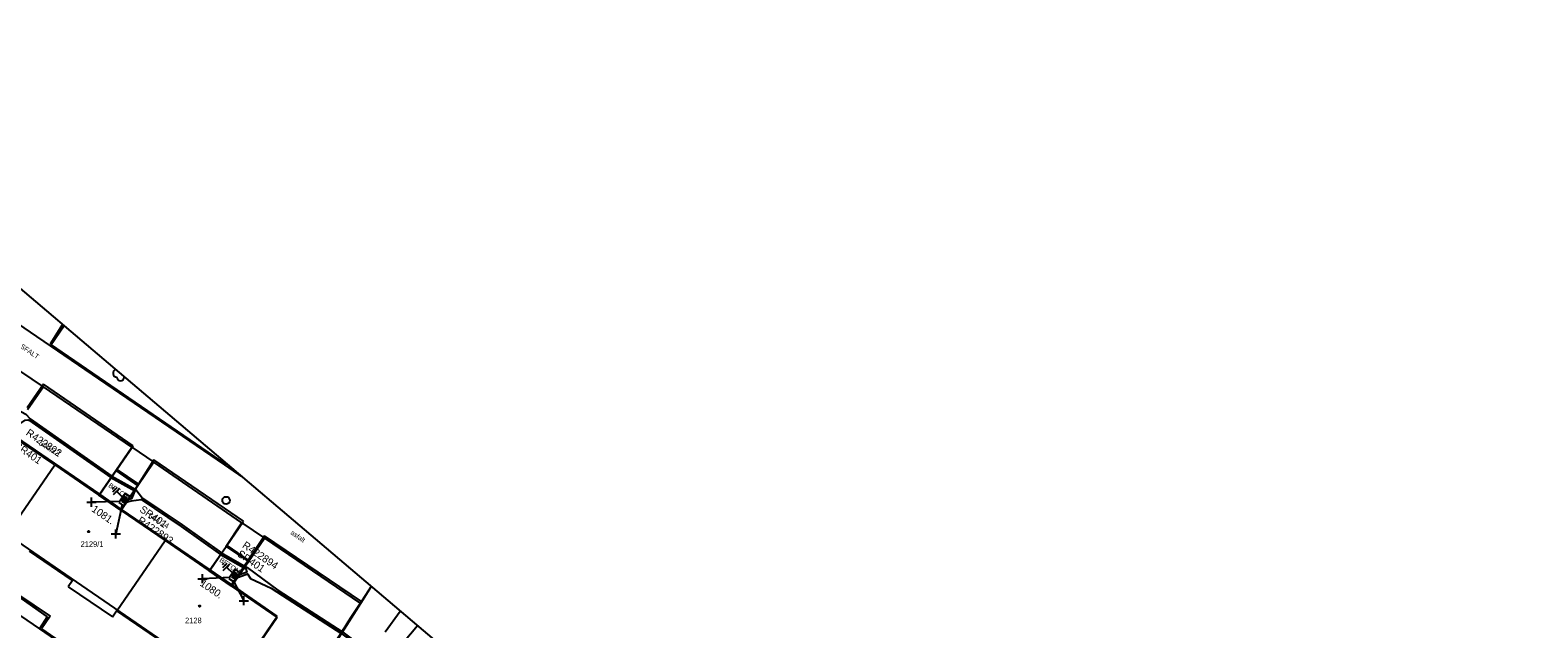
# Model space of a CAD drawing. Extents: x -540150 to -533593, y -1185082 to -1180066.
# Drawn here: x -536321.9 to -536119.2, y -1184312.1 to -1184231.5 of the extents above; entities that cross this region are included whole.
import ezdxf

# ---------------------------------------------------------------- set-up
doc = ezdxf.new("R2010")
doc.units = 0
for name, color, linetype in [('KN_HRAN_PARCEL', 7, 'Continuous'), ('KN_PARC_Č', 7, 'Continuous'), ('KN_VKP_HRAN_', 7, 'Continuous'), ('rámeček', 7, 'Continuous'), ('Vrstva 1', 7, 'Continuous'), ('Vrstva 10', 7, 'Continuous'), ('Vrstva 11', 7, 'Continuous'), ('Vrstva 14', 7, 'Continuous'), ('Vrstva 15', 7, 'Continuous'), ('Vrstva 22', 7, 'Continuous'), ('Vrstva 27', 7, 'Continuous'), ('Vrstva 28', 7, 'Continuous'), ('Vrstva 29', 7, 'Continuous'), ('Vrstva 30', 7, 'Continuous'), ('Vrstva 34', 7, 'Continuous'), ('Vrstva 39', 7, 'Continuous'), ('Vrstva 40', 7, 'Continuous'), ('Vrstva 47', 7, 'Continuous'), ('Vrstva 5', 7, 'Continuous'), ('Vrstva 59', 7, 'Continuous'), ('Vrstva 8', 7, 'Continuous')]:
    doc.layers.add(name, color=color, linetype=linetype)

# ---------------------------------------------------------------- blocks, each defined once
blk = doc.blocks.new('NN800')
at = {"layer": 'Vrstva 1'}
for points in [[(-0.44, 0.44), (0.44, -0.44)], [(-0.44, -0.44), (0.44, 0.44)]]:
    blk.add_lwpolyline(points, dxfattribs=at)
blk = doc.blocks.new('NN620')
at = {"layer": 'Vrstva 8'}
for points in [[(0.75, 0), (-0.75, 0)], [(-0.75, 0), (-0.75, -0.75)], [(0.75, -0.75), (0.75, 0)], [(-0.75, -0.75), (0.75, -0.75)], [(0.37, -0.18), (-0.38, -0.18)], [(-0.38, -0.18), (-0.38, -0.56)], [(-0.38, -0.56), (0.37, -0.56)], [(0.32, -0.23), (-0.33, -0.23)], [(-0.33, -0.23), (-0.33, -0.51)], [(-0.33, -0.51), (0.32, -0.51)], [(0.27, -0.27), (-0.28, -0.27)], [(-0.28, -0.27), (-0.28, -0.46)], [(-0.28, -0.46), (0.27, -0.46)], [(0.23, -0.32), (-0.23, -0.32)], [(-0.23, -0.32), (-0.23, -0.42)], [(-0.23, -0.42), (0.23, -0.42)], [(-0.19, -0.37), (0.19, -0.37)], [(0.23, -0.42), (0.23, -0.32)], [(0.27, -0.46), (0.27, -0.27)], [(0.32, -0.51), (0.32, -0.23)], [(0.37, -0.56), (0.37, -0.18)]]:
    blk.add_lwpolyline(points, dxfattribs=at)
blk = doc.blocks.new('NN810')
at = {"layer": 'Vrstva 14'}
for points in [[(0.63, -1.89), (-0.62, -1.89)], [(0, -0.64), (0, -1.89)], [(0.39, -2.2), (-0.4, -2.2)], [(0, -2.52), (-0.12, -2.52)], [(0.14, -2.52), (0, -2.52)]]:
    blk.add_lwpolyline(points, dxfattribs=at)

msp = doc.modelspace()

# ---------------------------------------------------------------- linework, layer by layer
at = {"layer": 'KN_HRAN_PARCEL'}
for p, q in [((-536317.32, -1184271.32), (-536319.16, -1184273.99)), ((-536295.72, -1184290.01), (-536319.16, -1184273.99)), ((-536320.09, -1184279.52), (-536323.12, -1184277.45)), ((-536320.09, -1184279.52), (-536322.23, -1184282.64)), ((-536308.21, -1184287.65), (-536320.09, -1184279.52)), ((-536318.58, -1184290.04), (-536324.51, -1184285.97)), ((-536310.37, -1184290.79), (-536308.21, -1184287.65)), ((-536308.21, -1184287.65), (-536305.26, -1184289.67)), ((-536325.06, -1184299.5), (-536318.58, -1184290.04)), ((-536318.58, -1184290.04), (-536312.64, -1184294.11)), ((-536305.26, -1184289.67), (-536307.4, -1184292.82)), ((-536293.42, -1184297.8), (-536305.26, -1184289.67)), ((-536295.56, -1184289.8), (-536295.72, -1184290.01)), ((-536312.64, -1184294.11), (-536310.37, -1184290.79)), ((-536293.94, -1184291.18), (-536293.97, -1184291.23)), ((-536293.97, -1184291.23), (-536293.49, -1184291.55)), ((-536307.4, -1184292.82), (-536309.67, -1184296.15)), ((-536309.67, -1184296.15), (-536303.75, -1184300.21)), ((-536295.55, -1184300.98), (-536293.42, -1184297.8)), ((-536293.42, -1184297.8), (-536290.4, -1184299.86)), ((-536310.23, -1184309.67), (-536303.75, -1184300.21)), ((-536303.75, -1184300.21), (-536297.81, -1184304.28)), ((-536292.55, -1184303.03), (-536290.4, -1184299.86)), ((-536290.4, -1184299.86), (-536277.49, -1184308.66)), ((-536316.19, -1184305.58), (-536321.99, -1184301.61)), ((-536297.81, -1184304.28), (-536295.55, -1184300.98)), ((-536294.82, -1184306.33), (-536292.55, -1184303.03)), ((-536326.19, -1184305.84), (-536319.61, -1184310.45)), ((-536316.19, -1184305.58), (-536316.76, -1184306.42)), ((-536316.76, -1184306.42), (-536310.83, -1184310.47)), ((-536294.82, -1184306.33), (-536288.69, -1184310.54)), ((-536276.06, -1184306.36), (-536277.49, -1184308.66)), ((-536310.83, -1184310.47), (-536310.27, -1184309.64)), ((-536310.23, -1184309.67), (-536310.27, -1184309.64)), ((-536301.47, -1184315.66), (-536310.23, -1184309.67)), ((-536277.49, -1184308.66), (-536287.35, -1184324.11)), ((-536274.16, -1184312.48), (-536272.15, -1184309.68)), ((-536319.61, -1184310.45), (-536320.65, -1184312.07)), ((-536320.65, -1184312.07), (-536292.11, -1184331.56)), ((-536288.69, -1184310.54), (-536295.17, -1184319.98))]:
    msp.add_line(p, q, dxfattribs=at)
at = {"layer": 'KN_VKP_HRAN_'}
for p, q in [((-536319.16, -1184273.99), (-536324.52, -1184270.34)), ((-536293.97, -1184291.23), (-536295.72, -1184290.01)), ((-536310.37, -1184290.79), (-536307.4, -1184292.82)), ((-536309.67, -1184296.15), (-536312.64, -1184294.11)), ((-536295.55, -1184300.98), (-536292.55, -1184303.03)), ((-536294.82, -1184306.33), (-536297.81, -1184304.28)), ((-536327.37, -1184307.46), (-536320.65, -1184312.07))]:
    msp.add_line(p, q, dxfattribs=at)
at = {"layer": 'rámeček'}
msp.add_lwpolyline([(-536863.36, -1184184.15), (-536677.59, -1183965.38), (-535884.86, -1184638.56), (-536070.63, -1184857.33)], close=True, dxfattribs=at)
at = {"layer": 'Vrstva 10'}
msp.add_lwpolyline([(-536276.03, -1184306.38), (-536276.36, -1184306.89), (-536276.85, -1184307.63), (-536277.34, -1184308.38), (-536278.67, -1184310.42), (-536279.17, -1184311.18), (-536279.6, -1184311.85), (-536279.98, -1184312.44), (-536280.31, -1184312.96), (-536280.88, -1184313.86), (-536281.31, -1184314.54), (-536281.62, -1184315.05)], dxfattribs=at)
at = {"layer": 'Vrstva 11'}
for p, q in [((-536317.52, -1184271.15), (-536319.21, -1184273.81)), ((-536319.21, -1184273.81), (-536295.6, -1184289.99)), ((-536320.11, -1184279.18), (-536322.27, -1184282.35)), ((-536308.04, -1184287.45), (-536320.11, -1184279.18)), ((-536310.23, -1184290.64), (-536308.04, -1184287.45)), ((-536305.26, -1184289.34), (-536307.34, -1184292.63)), ((-536293.22, -1184297.61), (-536305.26, -1184289.34)), ((-536295.51, -1184289.84), (-536295.6, -1184289.99)), ((-536312.53, -1184293.98), (-536310.23, -1184290.64)), ((-536310.23, -1184290.64), (-536307.34, -1184292.63)), ((-536309.63, -1184295.97), (-536307.34, -1184292.63)), ((-536295.46, -1184300.87), (-536293.22, -1184297.61)), ((-536290.37, -1184299.55), (-536292.56, -1184302.86)), ((-536277.34, -1184308.38), (-536290.37, -1184299.55)), ((-536297.71, -1184304.15), (-536295.46, -1184300.87)), ((-536295.46, -1184300.87), (-536292.56, -1184302.86)), ((-536294.81, -1184306.13), (-536292.56, -1184302.86)), ((-536325.76, -1184305.94), (-536319.2, -1184310.37)), ((-536319.2, -1184310.37), (-536320.36, -1184312.07)), ((-536320.36, -1184312.07), (-536292.09, -1184331.5))]:
    msp.add_line(p, q, dxfattribs=at)
at = {"layer": 'Vrstva 22'}
for centre, start, end in [((-536310.25, -1184277.71), 104.0477, 270), ((-536309.75, -1184278.21), 180, 0), ((-536309.25, -1184277.71), 270, 274.2448)]:
    msp.add_arc(centre, 0.5, start, end, dxfattribs=at)
at = {"layer": 'Vrstva 27'}
msp.add_circle((-536295.55, -1184294.8), 0.5, dxfattribs=at)
at = {"layer": 'Vrstva 39'}
for centre, radius in [((-536314.03, -1184298.99), 0.09), ((-536314.03, -1184298.99), 0.0398), ((-536299.11, -1184309.01), 0.09), ((-536299.11, -1184309.01), 0.0398)]:
    msp.add_circle(centre, radius, dxfattribs=at)
at = {"layer": 'Vrstva 5'}
for p, q in [((-536399.6, -1184248.11), (-536295.16, -1184319.85)), ((-536295.16, -1184319.85), (-536288.67, -1184310.35))]:
    msp.add_line(p, q, dxfattribs=at)
for points in [[(-536288.67, -1184310.35), (-536294.81, -1184306.13), (-536297.71, -1184304.15), (-536309.63, -1184295.97), (-536312.53, -1184293.98), (-536324.58, -1184285.71), (-536327.44, -1184283.76), (-536339.33, -1184275.6), (-536342.2, -1184273.63), (-536354.37, -1184265.28), (-536357.34, -1184263.25), (-536369.19, -1184255.11), (-536372.06, -1184253.15), (-536384.25, -1184244.79), (-536387.02, -1184242.88), (-536393.2, -1184238.65)], [(-536353.61, -1184264.18), (-536352.84, -1184264.16), (-536351.56, -1184263.85), (-536349.66, -1184264.7), (-536340.69, -1184271.37), (-536337.15, -1184273.12), (-536336.07, -1184274.15), (-536331.95, -1184277.16), (-536326.75, -1184280.93), (-536322.48, -1184283.19), (-536321.89, -1184283.83), (-536310.91, -1184291.52), (-536307.67, -1184293.32), (-536306.77, -1184294.49), (-536301.44, -1184298.1), (-536296.16, -1184301.85), (-536292.71, -1184303.81), (-536288.61, -1184306.86), (-536279.86, -1184312.52), (-536276.26, -1184315.21), (-536273.75, -1184317.25), (-536270.67, -1184318.65), (-536271.04, -1184319.92), (-536273.51, -1184322.6)], [(-536324.18, -1184285.13), (-536322.55, -1184284.03), (-536322.15, -1184283.96), (-536322.05, -1184284.02), (-536311.04, -1184291.73), (-536307.8, -1184293.53), (-536308.27, -1184294.6), (-536308.78, -1184294.72)], [(-536308.99, -1184295.03), (-536308.3, -1184294.87), (-536306.96, -1184294.66), (-536306.95, -1184294.68), (-536301.58, -1184298.31), (-536296.3, -1184302.06), (-536292.88, -1184303.99), (-536292.76, -1184304.44), (-536293.97, -1184304.91)], [(-536294.23, -1184305.28), (-536292.66, -1184304.66), (-536292.26, -1184305.32), (-536289.48, -1184306.6), (-536280, -1184312.73), (-536276.42, -1184315.4), (-536273.88, -1184317.46), (-536270.97, -1184318.79), (-536271.26, -1184319.79), (-536273.71, -1184322.46)], [(-536273.3, -1184322.75), (-536270.81, -1184320.05), (-536270.39, -1184318.58), (-536273.28, -1184315.64), (-536271.68, -1184313.89), (-536269.83, -1184311.65)]]:
    msp.add_lwpolyline(points, dxfattribs=at)
at = {"layer": 'Vrstva 59'}
for points in [[(-536309.85, -1184294.97), (-536313.63, -1184295.04)], [(-536309.5, -1184295.37), (-536310.38, -1184299.32)], [(-536295.05, -1184305.17), (-536298.71, -1184305.33)], [(-536294.58, -1184305.59), (-536293.16, -1184308.29)]]:
    msp.add_lwpolyline(points, dxfattribs=at)

# ---------------------------------------------------------------- block references
at = {"layer": 'Vrstva 15'}
for p, rotation in [((-536308.92, -1184294.91), -135), ((-536294.14, -1184305.1), -134.99999990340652)]:
    msp.add_blockref('NN810', p, dxfattribs=dict(at, rotation=rotation))
at = {"layer": 'Vrstva 28', "rotation": -124.45811942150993}
for p in [(-536308.92, -1184294.91), (-536294.14, -1184305.1)]:
    msp.add_blockref('NN620', p, dxfattribs=at)
at = {"layer": 'Vrstva 34', "rotation": 45}
for p in [(-536313.63, -1184295.04), (-536310.38, -1184299.32), (-536298.71, -1184305.33), (-536293.16, -1184308.29)]:
    msp.add_blockref('NN800', p, dxfattribs=at)

# ---------------------------------------------------------------- texts
at = {"layer": 'KN_PARC_Č'}
for s, p in [('544/23', (-536320.78, -1184287.32)), ('544/24', (-536306.13, -1184297.09))]:
    msp.add_text(s, height=0.75, rotation=329.4, dxfattribs=at).set_placement(p)
for s, p in [('2129/1', (-536315.1, -1184301.05)), ('2128', (-536301.06, -1184311.32))]:
    msp.add_text(s, height=0.75, dxfattribs=at).set_placement(p)
at = {"layer": 'Vrstva 29'}
for s, p in [('R422892', (-536322.55, -1184285.93)), ('R422893', (-536307.55, -1184297.71)), ('R422894', (-536293.46, -1184301.06))]:
    msp.add_text(s, height=1, rotation=325.542, dxfattribs=at).set_placement(p)
at = {"layer": 'Vrstva 30'}
for p in [(-536324.11, -1184287.68), (-536307.26, -1184296.24), (-536294.14, -1184302.23)]:
    msp.add_text('SR401', height=1, rotation=325.542, dxfattribs=at).set_placement(p)
at = {"layer": 'Vrstva 40'}
for s, rotation, p in [('ASFALT', 325.577, (-536323.76, -1184273.91)), ('BETON', 325.5527, (-536311.43, -1184292.95)), ('asfalt', 325.3725, (-536286.95, -1184299.29)), ('BETON', 325.5527, (-536296.51, -1184302.97))]:
    msp.add_text(s, height=0.65, rotation=rotation, dxfattribs=at).set_placement(p)
at = {"layer": 'Vrstva 47'}
for s, p in [('1081.', (-536313.72, -1184296.2)), ('1080.', (-536299.15, -1184306.19))]:
    msp.add_text(s, height=1, rotation=325.5527, dxfattribs=at).set_placement(p)

doc.saveas('drawing.dxf')
